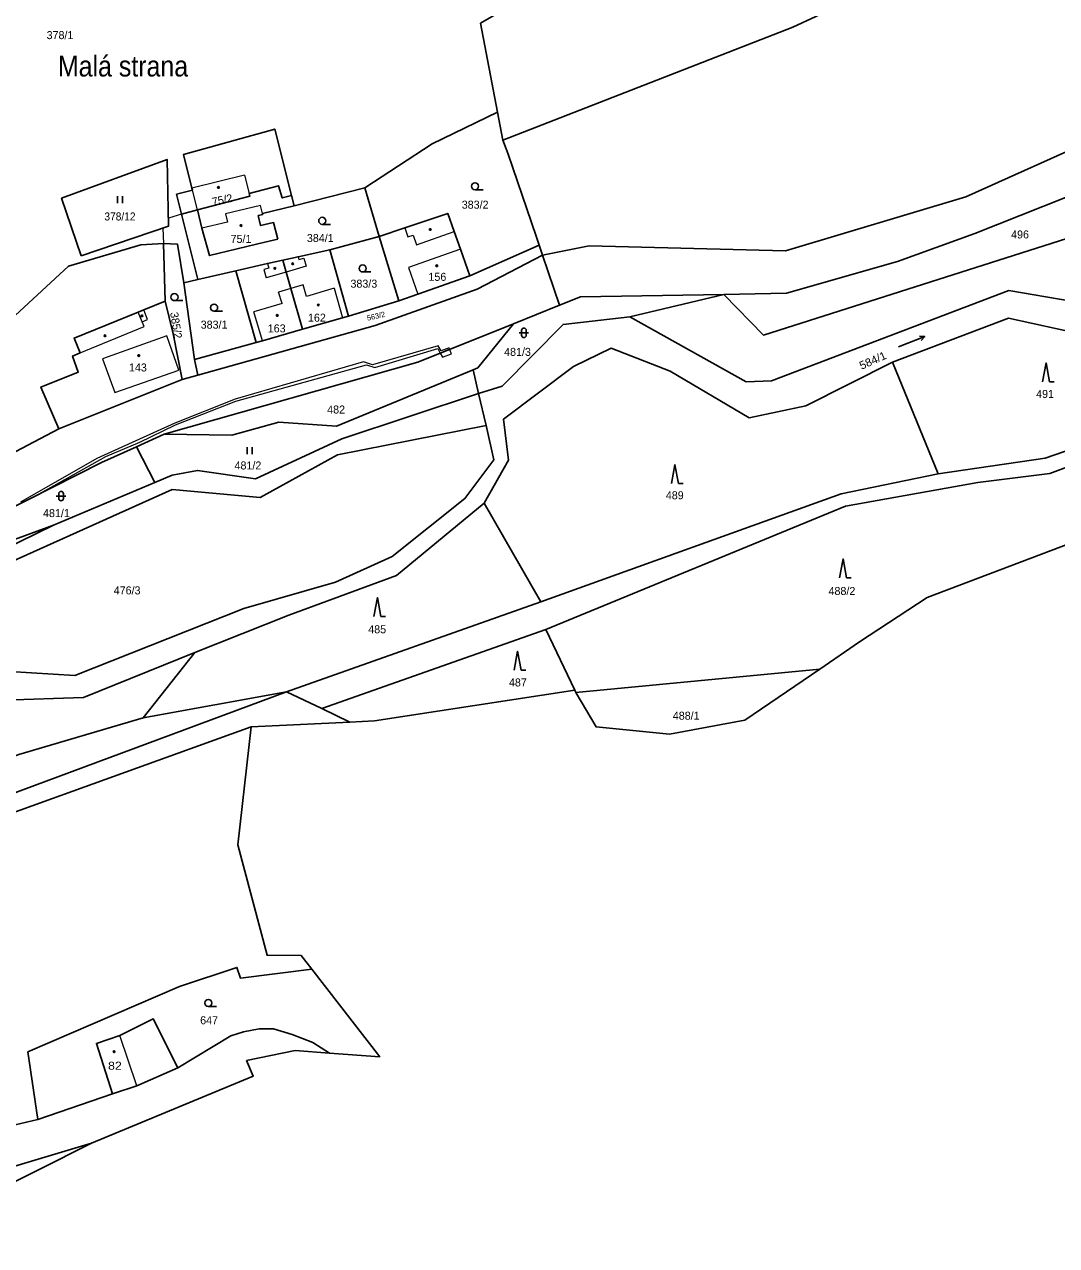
# Model space of a CAD drawing. Extents: x -754445 to -751443, y -1030748 to -1028224.
# Drawn here: x -753097.8 to -752878.6, y -1029035.5 to -1028776.1 of the extents above; entities that cross this region are included whole.
import ezdxf
from ezdxf.enums import TextEntityAlignment as Align

# ---------------------------------------------------------------- set-up
doc = ezdxf.new("R2010")
doc.units = 0
doc.header["$LTSCALE"] = 0.68
for name, color, linetype, lineweight in [('1', 7, 'Continuous', 25), ('13', 7, 'Continuous', 13), ('3', 7, 'Continuous', 25), ('4', 7, 'Continuous', 13), ('5', 7, 'Continuous', 25), ('7', 7, 'Continuous', 13)]:
    doc.layers.add(name, color=color, linetype=linetype, lineweight=lineweight)
doc.layers.add('2', color=7, linetype='Continuous')

msp = doc.modelspace()

# ---------------------------------------------------------------- linework, layer by layer
at = {"layer": '1'}
for p, q in [((-752997.35, -1028794.77), (-752996.21, -1028800.72)), ((-752995.48, -1028802.6), (-752996.21, -1028800.72)), ((-752995.04, -1028803.73), (-752995.48, -1028802.6)), ((-753040.53, -1028814.64), (-753025.52, -1028810.86)), ((-753025.52, -1028810.86), (-753022.42, -1028821.18)), ((-753040.53, -1028814.64), (-753041.07, -1028812.51)), ((-753064.42, -1028816.45), (-753061.04, -1028815.55)), ((-753043.98, -1028821.77), (-753044.87, -1028818.24)), ((-753022.42, -1028821.18), (-753032.95, -1028823.99)), ((-753022.42, -1028821.18), (-753018.3, -1028834.87)), ((-753067.86, -1028834.93), (-753068.26, -1028822.65)), ((-752987.76, -1028825.13), (-752988.48, -1028823.01)), ((-752987.76, -1028825.13), (-752984.15, -1028835.78)), ((-753052.87, -1028828.46), (-753060.96, -1028830.33)), ((-753063.95, -1028831.02), (-753061.65, -1028847.34)), ((-753028.95, -1028838.07), (-753018.3, -1028834.87)), ((-752984.15, -1028835.78), (-752993.95, -1028839.71)), ((-753061.65, -1028847.34), (-753048.54, -1028843.68)), ((-753061.65, -1028847.34), (-753060.98, -1028850.62)), ((-753060.98, -1028850.62), (-753064.31, -1028851.59)), ((-753090.47, -1028862.01), (-753064.31, -1028851.59)), ((-753001.33, -1028854.51), (-752999.76, -1028861.33)), ((-753090.47, -1028862.01), (-753134.8, -1028885.38)), ((-753068.12, -1028863.17), (-753073.97, -1028865.83)), ((-753070.11, -1028873.45), (-753073.97, -1028865.83)), ((-753091.6, -1028882.51), (-753070.11, -1028873.45)), ((-753072.54, -1028923.37), (-753061.57, -1028909.5)), ((-752928.9, -1028913.07), (-752980.65, -1028917.99)), ((-753042.14, -1028917.9), (-753072.54, -1028923.37)), ((-752980.93, -1028917.5), (-752980.65, -1028917.99)), ((-753094.96, -1029008.68), (-753079.08, -1029003.24))]:
    msp.add_line(p, q, dxfattribs=at)
for points in [[(-752997.35, -1028794.77), (-753000.96, -1028775.89), (-752968.4, -1028757.04), (-752942.88, -1028733.82), (-752956.28, -1028720.59)], [(-752996.21, -1028800.72), (-752934.62, -1028776.73), (-752919.93, -1028769.88), (-752915.16, -1028767.66)], [(-752817.23, -1028776.57), (-752827.17, -1028784.49), (-752841.76, -1028795.31), (-752866.7, -1028808.91), (-752895.95, -1028820.56), (-752912.35, -1028826.5), (-752935.94, -1028833.24), (-752949.28, -1028833.47)], [(-752842.87, -1028783.6), (-752869.51, -1028800.05), (-752897.89, -1028812.79), (-752936.14, -1028824.21), (-752977.85, -1028823.19), (-752987.76, -1028825.13)], [(-752813.8, -1028782.8), (-752863.56, -1028817.52), (-752940.85, -1028842.12), (-752949.28, -1028833.47)], [(-752969.25, -1028838.22), (-752944.55, -1028852.04), (-752939.16, -1028851.86), (-752888.77, -1028832.69), (-752875.53, -1028834.9), (-752859.74, -1028828.82), (-752840.76, -1028809.81), (-752817.4, -1028796.03), (-752811.45, -1028787.06)], [(-753025.52, -1028810.86), (-753011.22, -1028801.54), (-752997.35, -1028794.77)], [(-753041.07, -1028812.51), (-753044.63, -1028798.39), (-753064.01, -1028803.8), (-753062.23, -1028810.94), (-753062.12, -1028811.38), (-753065.47, -1028812.21), (-753064.42, -1028816.45)], [(-753003.2, -1028829.57), (-752988.48, -1028823.01), (-752989.11, -1028821.14), (-752995.04, -1028803.73)], [(-753041.07, -1028812.51), (-753043.01, -1028813), (-753043.8, -1028810.42), (-753050.02, -1028812.07), (-753049.88, -1028812.59), (-753061.04, -1028815.55)], [(-753044.87, -1028818.24), (-753047.63, -1028818.87), (-753048.13, -1028816.75), (-753047.18, -1028816.52), (-753047.23, -1028816.33), (-753040.53, -1028814.64)], [(-753068.26, -1028822.65), (-753065.24, -1028822.84), (-753063.95, -1028831.02), (-753060.96, -1028830.33), (-753064.42, -1028816.45)], [(-753061.04, -1028815.55), (-753060.09, -1028819.44), (-753058.47, -1028825.25), (-753046.75, -1028822.41), (-753043.98, -1028821.77)], [(-753003.2, -1028829.57), (-753005.2, -1028823.86), (-753006.51, -1028820.14), (-753007.87, -1028816.27), (-753017.01, -1028819.36), (-753022.42, -1028821.18)], [(-753134.58, -1028872.67), (-753132.43, -1028873.36), (-753122.96, -1028866.17), (-753117.58, -1028856.31), (-753106.38, -1028852.88), (-753112.03, -1028849.29), (-753088.4, -1028827.5), (-753073.04, -1028822.98), (-753068.26, -1028822.65)], [(-752987.76, -1028825.13), (-753001.67, -1028832.4), (-753023.32, -1028840.12), (-753060.98, -1028850.62)], [(-753032.95, -1028823.99), (-753039.66, -1028825.47), (-753042.92, -1028826.19)], [(-753038.73, -1028840.89), (-753030.23, -1028838.45), (-753028.95, -1028838.07), (-753032.95, -1028823.99)], [(-753042.92, -1028826.19), (-753046.18, -1028826.91), (-753052.87, -1028828.46), (-753048.54, -1028843.68)], [(-753042.92, -1028826.19), (-753042.19, -1028828.73), (-753041.2, -1028832.21), (-753038.73, -1028840.89)], [(-753018.3, -1028834.87), (-753014.24, -1028833.45), (-753003.2, -1028829.57)], [(-753067.86, -1028834.93), (-753072.45, -1028836.79), (-753073.6, -1028837.25), (-753087.23, -1028842.77), (-753085.96, -1028845.91), (-753087.55, -1028846.57), (-753086.34, -1028850), (-753094.28, -1028853.17), (-753090.47, -1028862.01)], [(-753064.31, -1028851.59), (-753066.19, -1028841.88), (-753067.86, -1028834.93)], [(-753001.33, -1028854.51), (-752996.35, -1028852.96), (-752983.4, -1028839.84), (-752969.25, -1028838.22), (-752949.28, -1028833.47)], [(-752949.28, -1028833.47), (-752979.68, -1028833.98), (-752984.15, -1028835.78)], [(-752858.73, -1028836.29), (-752873.32, -1028841.91), (-752888.84, -1028838.56), (-752913.41, -1028847.84)], [(-752993.95, -1028839.71), (-753014.26, -1028847.84), (-753068.12, -1028863.17)], [(-752993.95, -1028839.71), (-753001.53, -1028849.1), (-753002.49, -1028849.49)], [(-753048.54, -1028843.68), (-753047.23, -1028843.31), (-753038.73, -1028840.89)], [(-752913.41, -1028847.84), (-752931.86, -1028857.14), (-752943.9, -1028859.73), (-752960.65, -1028849.8), (-752973.2, -1028844.89), (-752981.18, -1028848.77), (-752996.01, -1028859.97), (-752994.95, -1028868.72), (-753000.18, -1028877.79)], [(-752988.13, -1028898.77), (-752924.36, -1028875.8), (-752903.77, -1028871.6), (-752913.41, -1028847.84)], [(-753070.11, -1028873.45), (-753066.37, -1028871.87), (-753061.04, -1028870.85), (-753048.73, -1028872.67), (-753030.4, -1028864.19), (-753001.33, -1028854.51), (-753002.49, -1028849.49)], [(-753002.49, -1028849.49), (-753031.51, -1028861.46), (-753043.72, -1028860.6), (-753053.72, -1028863.37), (-753068.12, -1028863.17)], [(-752999.76, -1028861.33), (-753031.31, -1028867.54), (-753047.75, -1028876.58), (-753066.39, -1028874.93), (-753108.51, -1028893.85), (-753136.48, -1028902.04), (-753157.46, -1028920.58), (-753161.4, -1028921.14)], [(-753156.24, -1028928.95), (-753147.31, -1028923.08), (-753100.88, -1028913.59), (-753087.08, -1028914.44), (-753051.19, -1028900.21), (-753031.73, -1028894.6), (-753019.72, -1028889.12), (-753004.25, -1028876.84), (-752998.07, -1028868.64), (-752999.76, -1028861.33)], [(-752903.77, -1028871.6), (-752881.02, -1028868.26), (-752855, -1028859.24)], [(-752854.6, -1028862.01), (-752880.03, -1028871.5), (-752895.33, -1028873.44), (-752923.42, -1028878.46), (-752987.06, -1028904.67)], [(-752906.11, -1028897.87), (-752864.28, -1028881.96), (-752850.6, -1028876.91), (-752854.6, -1028862.01)], [(-753073.97, -1028865.83), (-753081.42, -1028869.21), (-753107.45, -1028882.38), (-753129.56, -1028892.89)], [(-753000.18, -1028877.79), (-753018.78, -1028893.15), (-753041.63, -1028901.58), (-753061.57, -1028909.5)], [(-753042.14, -1028917.9), (-752988.13, -1028898.77), (-753000.18, -1028877.79)], [(-753216.41, -1028934.77), (-753207.44, -1028936.69), (-753177, -1028920.55), (-753158.6, -1028917.93), (-753138.66, -1028899.83), (-753109.83, -1028891.4), (-753091.6, -1028882.51)], [(-753091.6, -1028882.51), (-753112.3, -1028890.06), (-753129.56, -1028892.89)], [(-752928.9, -1028913.07), (-752920.44, -1028907.28), (-752906.11, -1028897.87)], [(-753028.66, -1028924.3), (-753023.45, -1028924.05), (-752980.93, -1028917.5), (-752987.06, -1028904.67), (-753034.6, -1028921.39)], [(-753061.57, -1028909.5), (-753085.23, -1028919.06), (-753102.18, -1028919.63), (-753147.2, -1028928.97), (-753199.09, -1028965.99), (-753214.67, -1028983.44), (-753227.91, -1029002.35), (-753239.27, -1029023.03)], [(-752980.65, -1028917.99), (-752976.37, -1028925.35), (-752960.76, -1028926.85), (-752944.78, -1028923.93), (-752928.9, -1028913.07)], [(-753042.14, -1028917.9), (-753106.78, -1028941.85), (-753138.13, -1028951.79), (-753188.66, -1028988.29), (-753227.66, -1029024.5), (-753269.09, -1029062.17), (-753299.36, -1029096.33)], [(-753049.6, -1028925.31), (-753028.66, -1028924.3), (-753034.6, -1028921.39), (-753042.14, -1028917.9)], [(-753072.54, -1028923.37), (-753098.97, -1028931.22), (-753141.59, -1028946.89), (-753151.77, -1028952.05), (-753164.86, -1028962.85), (-753177.15, -1028966.98), (-753227.57, -1029012.56), (-753239.27, -1029023.03)], [(-753049.6, -1028925.31), (-753103.08, -1028944.56), (-753136.56, -1028959.62), (-753164.51, -1028979.55), (-753197.36, -1029005.36), (-753221.21, -1029025.61), (-753231.65, -1029036.2), (-753263.95, -1029066.84), (-753289.3, -1029094.11), (-753299.36, -1029096.33), (-753321.63, -1029103.19)], [(-753036.77, -1028976.78), (-753039, -1028973.9), (-753046.24, -1028973.83), (-753052.47, -1028950.37), (-753049.6, -1028925.31)], [(-753094.96, -1029008.68), (-753097.03, -1028994.35), (-753064.87, -1028980.44), (-753052.67, -1028976.41), (-753051.89, -1028978.71), (-753036.77, -1028976.78)], [(-753032.97, -1028994.61), (-753022.31, -1028995.39), (-753036.77, -1028976.78)], [(-753065.19, -1028997.74), (-753070.46, -1028987.31), (-753077.54, -1028990.85), (-753082.49, -1028992.54), (-753079.08, -1029003.24)], [(-753065.19, -1028997.74), (-753053.94, -1028990.95), (-753051.22, -1028990.07), (-753047.94, -1028989.48), (-753044.91, -1028989.48), (-753040.92, -1028990.65), (-753036.55, -1028992.34), (-753032.97, -1028994.61)], [(-753117.68, -1029030.87), (-753083.51, -1029013.75), (-753049.19, -1028999.5), (-753050.62, -1028996.17)], [(-753050.62, -1028996.17), (-753040.28, -1028994.07), (-753032.97, -1028994.61)], [(-753079.08, -1029003.24), (-753073.87, -1029001.58), (-753065.19, -1028997.74)], [(-753272.08, -1029104.35), (-753257.32, -1029089.93), (-753209.56, -1029049.56), (-753191.33, -1029038.68), (-753125.1, -1029015.75), (-753094.96, -1029008.68)], [(-753258.72, -1029106.42), (-753258.82, -1029103.04), (-753254.14, -1029097.3), (-753204.68, -1029055.84), (-753188.6, -1029046.26), (-753164.24, -1029037.55), (-753135.98, -1029029.42), (-753083.51, -1029013.75)]]:
    msp.add_lwpolyline(points, dxfattribs=at)
msp.add_lwpolyline([(-753085.72, -1028825.27), (-753089.87, -1028813.06), (-753067.48, -1028804.83), (-753067.16, -1028818.98)], close=True, dxfattribs=at)
at = {"layer": '13'}
for points in [[(-753067.2, -1028817.32), (-753067.16, -1028818.98), (-753068.37, -1028819.39), (-753068.26, -1028822.65), (-753065.24, -1028822.84), (-753063.95, -1028831.02), (-753060.96, -1028830.33), (-753064.42, -1028816.45)], [(-753007.1, -1028846.1), (-753007.48, -1028845.12), (-753009.48, -1028845.93), (-753008.97, -1028846.84)]]:
    msp.add_lwpolyline(points, close=True, dxfattribs=at)
msp.add_lwpolyline([(-753099.5, -1028878.36), (-753096.13, -1028876.65), (-753080.46, -1028867.92), (-753073.24, -1028864.86), (-753065.69, -1028861.2), (-753052.87, -1028856.13), (-753025.13, -1028848.41), (-753023.36, -1028848.99), (-753010.02, -1028844.98), (-753009.48, -1028845.93), (-753007.48, -1028845.12), (-753007.59, -1028844.83), (-753009.29, -1028845.45), (-753009.89, -1028844.39), (-753023.85, -1028848.41), (-753025.77, -1028847.79), (-753052.99, -1028855.75), (-753065.85, -1028860.84), (-753082.4, -1028868.35), (-753098.62, -1028877.58)], dxfattribs=at)
at = {"layer": '3'}
for p, q in [((-753002.093, -1028811.27), (-753000.343, -1028811.27)), ((-753077.981, -1028814.12), (-753077.981, -1028812.62)), ((-753076.98, -1028814.12), (-753076.98, -1028812.62)), ((-753034.543, -1028818.61), (-753032.793, -1028818.61)), ((-753025.953, -1028828.72), (-753024.203, -1028828.72)), ((-753065.913, -1028834.81), (-753064.163, -1028834.81)), ((-753057.493, -1028837.05), (-753055.743, -1028837.05)), ((-752992.711, -1028841.641), (-752990.709, -1028841.641)), ((-752992.211, -1028841.141), (-752992.211, -1028842.142)), ((-752991.209, -1028842.142), (-752991.209, -1028841.141)), ((-752906.6, -1028842.437), (-752907.333, -1028843.255)), ((-752880.08, -1028852.04), (-752879.084, -1028852.04)), ((-753050.451, -1028867.4), (-753050.451, -1028865.9)), ((-753049.45, -1028867.4), (-753049.45, -1028865.9)), ((-752958.88, -1028873.66), (-752957.884, -1028873.66)), ((-753091.001, -1028876.311), (-753088.999, -1028876.311)), ((-753090.501, -1028875.811), (-753090.501, -1028876.812)), ((-753089.499, -1028876.812), (-753089.499, -1028875.811)), ((-752923.18, -1028893.64), (-752922.184, -1028893.64)), ((-753022.08, -1028901.85), (-753021.084, -1028901.85)), ((-752992.31, -1028913.28), (-752991.314, -1028913.28)), ((-753058.723, -1028984.71), (-753056.973, -1028984.71))]:
    msp.add_line(p, q, dxfattribs=at)
for points in [[(-752912.202, -1028844.587), (-752906.6, -1028842.437), (-752907.692, -1028842.319)], [(-752880.08, -1028852.04), (-752880.83, -1028848.04), (-752881.58, -1028852.04)], [(-752958.88, -1028873.66), (-752959.63, -1028869.66), (-752960.38, -1028873.66)], [(-752923.18, -1028893.64), (-752923.93, -1028889.64), (-752924.68, -1028893.64)], [(-753022.08, -1028901.85), (-753022.83, -1028897.85), (-753023.58, -1028901.85)], [(-752992.31, -1028913.28), (-752993.06, -1028909.28), (-752993.81, -1028913.28)]]:
    msp.add_lwpolyline(points, dxfattribs=at)
for centre in [(-753002.0929, -1028810.5198), (-753034.5429, -1028817.8598), (-753025.9529, -1028827.9698), (-753065.9129, -1028834.0598), (-753057.4929, -1028836.2998), (-753058.7229, -1028983.9598)]:
    msp.add_circle(centre, 0.75, dxfattribs=at)
for centre, start, end in [((-752991.71, -1028841.1409), 0, 180), ((-752991.71, -1028842.1409), 180, 359.98789), ((-753090, -1028875.8109), 0, 180), ((-753090, -1028876.8109), 180, 359.98789)]:
    msp.add_arc(centre, 0.5, start, end, dxfattribs=at)
at = {"layer": '4'}
for p, q in [((-753051.06, -1028808.15), (-753062.23, -1028810.94)), ((-753051.06, -1028808.15), (-753050.02, -1028812.07)), ((-753061.04, -1028815.55), (-753062.12, -1028811.38)), ((-753047.68, -1028814.59), (-753055.06, -1028816.38)), ((-753047.23, -1028816.33), (-753047.68, -1028814.59)), ((-753055.06, -1028816.38), (-753054.63, -1028818.12)), ((-753054.63, -1028818.12), (-753060.09, -1028819.44)), ((-753017.01, -1028819.36), (-753016.34, -1028821.26)), ((-753016.34, -1028821.26), (-753015.26, -1028820.88)), ((-753015.26, -1028820.88), (-753014.53, -1028822.96)), ((-753014.53, -1028822.96), (-753006.51, -1028820.14)), ((-753005.2, -1028823.86), (-753016.24, -1028827.74)), ((-753046.18, -1028826.91), (-753045.89, -1028827.91)), ((-753037.93, -1028827.51), (-753042.19, -1028828.73)), ((-753039.66, -1028825.47), (-753039.48, -1028826.08)), ((-753039.48, -1028826.08), (-753038.42, -1028825.78)), ((-753038.42, -1028825.78), (-753037.93, -1028827.51)), ((-753016.24, -1028827.74), (-753014.24, -1028833.45)), ((-753045.89, -1028827.91), (-753046.95, -1028828.22)), ((-753046.95, -1028828.22), (-753046.46, -1028829.95)), ((-753042.19, -1028828.73), (-753046.46, -1028829.95)), ((-753041.2, -1028832.21), (-753043.79, -1028832.98)), ((-753038.61, -1028831.44), (-753041.2, -1028832.21)), ((-753037.88, -1028833.92), (-753038.61, -1028831.44)), ((-753032.03, -1028832.19), (-753037.88, -1028833.92)), ((-753032.03, -1028832.19), (-753030.23, -1028838.45)), ((-753043.06, -1028835.45), (-753049.03, -1028837.22)), ((-753043.06, -1028835.45), (-753043.79, -1028832.98)), ((-753072.78, -1028839.29), (-753073.6, -1028837.25)), ((-753071.63, -1028838.83), (-753072.45, -1028836.79)), ((-753047.23, -1028843.31), (-753049.03, -1028837.22)), ((-753085.96, -1028845.91), (-753072.36, -1028840.31)), ((-753072.78, -1028839.29), (-753071.63, -1028838.83)), ((-753072.36, -1028840.31), (-753072.78, -1028839.29)), ((-753067.51, -1028842.28), (-753081.17, -1028847.2)), ((-753065.01, -1028849.56), (-753067.51, -1028842.28)), ((-753081.17, -1028847.2), (-753078.59, -1028854.34)), ((-753078.59, -1028854.34), (-753065.01, -1028849.56)), ((-753073.87, -1029001.58), (-753077.54, -1028990.85))]:
    msp.add_line(p, q, dxfattribs=at)
at = {"layer": '5'}
for centre in [(-753056.5768, -1028810.7692), (-753051.7868, -1028818.8592), (-753011.6068, -1028819.6992), (-753044.5868, -1028827.9592), (-753040.7968, -1028826.9892), (-753010.2168, -1028827.4092), (-753035.3768, -1028835.7392), (-753072.8068, -1028838.0392), (-753044.0968, -1028837.9492), (-753080.6568, -1028842.2692), (-753073.4868, -1028846.4692), (-753078.7268, -1028994.3092)]:
    msp.add_circle(centre, 0.175, dxfattribs=at)

# ---------------------------------------------------------------- texts
at = {"layer": '2'}
for s, p in [('378/1', (-753090.22, -1028779.27)), ('383/2', (-753002.07, -1028815.28)), ('496', (-752886.359, -1028821.6)), ('75/1', (-753051.78, -1028822.55)), ('384/1', (-753034.95, -1028822.36)), ('383/3', (-753025.7, -1028832.05)), ('156', (-753010.089, -1028830.6)), ('162', (-753035.669, -1028839.28)), ('383/1', (-753057.5, -1028840.76)), ('163', (-753044.209, -1028841.55)), ('481/3', (-752993.07, -1028846.54)), ('143', (-753073.679, -1028849.85)), ('491', (-752881.049, -1028855.47)), ('482', (-753031.589, -1028858.78)), ('481/2', (-753050.31, -1028870.66)), ('489', (-752959.679, -1028876.99)), ('481/1', (-753090.98, -1028880.78)), ('476/3', (-753075.97, -1028897.19)), ('488/2', (-752924.18, -1028897.32)), ('485', (-753022.869, -1028905.45)), ('487', (-752992.989, -1028916.74)), ('488/1', (-752957.25, -1028923.8)), ('647', (-753058.559, -1028988.48))]:
    msp.add_text(s, height=1.7, dxfattribs=at).set_placement(p, align=Align.CENTER)
for s, height, rotation, p in [('75/2', 1.7, 12, (-753055.5952, -1028814.236)), ('385/2', 1.7, 279, (-753066.3952, -1028840.1805)), ('563/2', 1.14, 13, (-753022.9957, -1028838.645))]:
    msp.add_text(s, height=height, rotation=rotation, dxfattribs=at).set_placement(p, align=Align.CENTER)
for s, width, p in [('378/12', 0.95, (-753077.489, -1028817.78)), ('82', 1.15, (-753078.56, -1028998.13))]:
    msp.add_text(s, height=1.7, dxfattribs=dict(at, width=width)).set_placement(p, align=Align.CENTER)
at = {"layer": '2', "width": 1.05}
msp.add_text('584/1', height=1.7, rotation=24, dxfattribs=at).set_placement((-752917.2832, -1028848.2835), align=Align.CENTER)
at = {"layer": '7', "width": 0.9}
msp.add_text('Malá strana', height=4.4, dxfattribs=at).set_placement((-753076.839, -1028787.208), align=Align.CENTER)

doc.saveas('drawing.dxf')
